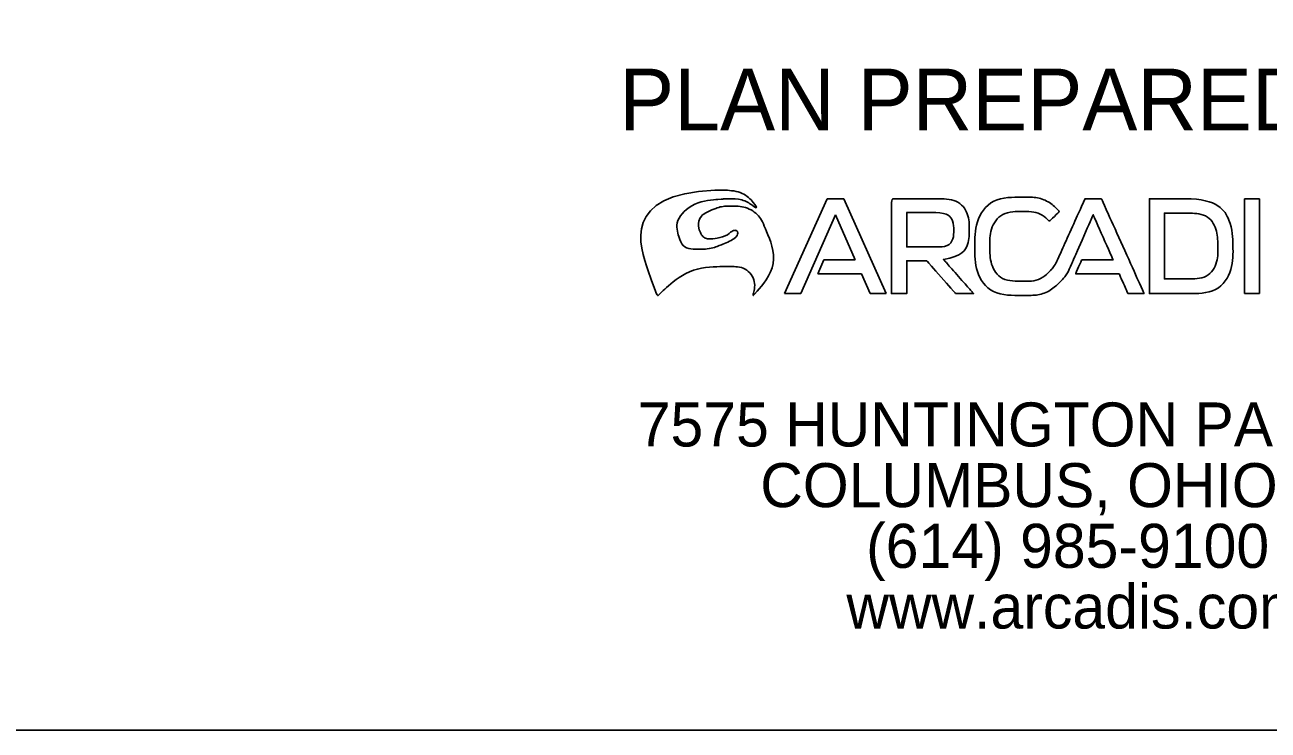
# Model space of a CAD drawing. Extents: x 0 to 45.4, y -2.2 to 22.
# Drawn here: x 2.903 to 5.724, y 0.5 to 2.102 of the extents above; entities that cross this region are included whole.
import ezdxf

# ---------------------------------------------------------------- set-up
doc = ezdxf.new("R2010")
doc.units = 0
for name, color, linetype in [('SH_Border', 7, 'Continuous'), ('SH_Data', 7, 'Continuous'), ('SH_Text', 7, 'Continuous')]:
    doc.layers.add(name, color=color, linetype=linetype)

msp = doc.modelspace()

# ---------------------------------------------------------------- linework, layer by layer
at = {"layer": 'SH_Border'}
msp.add_lwpolyline([(1.5, 21.5), (33.5, 21.5), (33.5, 0.5), (1.5, 0.5)], close=True, dxfattribs=at)
at = {"layer": 'SH_Data'}
for p, q in [((4.7232, 1.7068), (4.6265, 1.4914)), ((4.7607, 1.7068), (4.7232, 1.7068)), ((4.8574, 1.4914), (4.7607, 1.7068)), ((5.7044, 1.7068), (5.6702, 1.7068)), ((5.6702, 1.7068), (5.6702, 1.4914)), ((5.7044, 1.4914), (5.7044, 1.7068)), ((4.6632, 1.4914), (4.7419, 1.6705)), ((4.7419, 1.6705), (4.787, 1.568)), ((4.7158, 1.568), (4.7019, 1.5366)), ((4.787, 1.568), (4.7158, 1.568)), ((4.7019, 1.5366), (4.8008, 1.5366)), ((4.8008, 1.5366), (4.8207, 1.4914)), ((4.6265, 1.4914), (4.6632, 1.4914)), ((4.8207, 1.4914), (4.8574, 1.4914)), ((5.6702, 1.4914), (5.7044, 1.4914)), ((5.1819, 1.2488), (5.1819, 1.2488)), ((5.1819, 1.2488), (5.1819, 1.2488)), ((5.1819, 1.2488), (5.1819, 1.2488)), ((5.1819, 1.2488), (5.1819, 1.2488)), ((5.1819, 1.2488), (5.1819, 1.2488))]:
    msp.add_line(p, q, dxfattribs=at)
for points, degree in [([(4.4684, 1.7265), (4.2565, 1.7172), (4.3378, 1.4846), (4.3378, 1.4846), (4.3563, 1.5046), (4.4158, 1.5524), (4.4992, 1.5528), (4.4993, 1.5528), (4.4994, 1.5528), (4.4995, 1.5528), (4.5397, 1.5528), (4.5634, 1.5186), (4.5542, 1.4846), (4.5542, 1.4846), (4.6169, 1.558), (4.582, 1.6416), (4.5704, 1.6694), (4.5392, 1.6901), (4.5027, 1.6901), (4.4903, 1.6901), (4.4773, 1.6878), (4.4643, 1.6825), (4.4337, 1.6701), (4.4296, 1.6425), (4.4359, 1.6297), (4.4405, 1.6203), (4.4495, 1.6157), (4.4593, 1.6157), (4.461, 1.6157), (4.4626, 1.6158), (4.4643, 1.6161), (4.495, 1.6209), (4.5075, 1.6351), (4.5146, 1.6351), (4.5156, 1.6351), (4.5165, 1.6348), (4.5174, 1.6342), (4.5219, 1.6307), (4.5175, 1.6162), (4.4782, 1.6004), (4.4687, 1.5966), (4.4513, 1.5921), (4.4341, 1.5921), (4.414, 1.5921), (4.3943, 1.5982), (4.3877, 1.6184), (4.3753, 1.656), (4.4196, 1.701), (4.486, 1.7062), (4.4893, 1.7065), (4.4939, 1.7066), (4.4971, 1.7066), (4.5309, 1.7066), (4.5551, 1.6914), (4.5671, 1.6814), (4.5533, 1.7044), (4.5244, 1.7257), (4.4776, 1.7265), (4.4776, 1.7265), (4.4738, 1.7266), (4.4684, 1.7265), (4.4684, 1.7265), (4.4684, 1.7265), (4.4684, 1.7265)], 3), ([(4.9871, 1.5692), (5.0296, 1.5754), (5.0456, 1.6056), (5.0456, 1.6363), (5.0456, 1.6727), (5.0194, 1.7068), (4.9695, 1.7068), (4.936, 1.7068), (4.9028, 1.7068), (4.8692, 1.7068), (4.8692, 1.7068), (4.8692, 1.4914), (4.8692, 1.4914), (4.8692, 1.4914), (4.9037, 1.4914), (4.9037, 1.4914), (4.9037, 1.4914), (4.9037, 1.5659), (4.9037, 1.5659), (4.9037, 1.5659), (4.9492, 1.5659), (4.9492, 1.5659), (4.9492, 1.5659), (5.0148, 1.4914), (5.0148, 1.4914), (5.0148, 1.4914), (5.0552, 1.4914), (5.0552, 1.4914)], 3), ([(5.3456, 1.7068), (5.3456, 1.7068), (5.3081, 1.7068), (5.3081, 1.7068), (5.3081, 1.7068), (5.2454, 1.5671), (5.2454, 1.5671), (5.2454, 1.5671), (5.2454, 1.5671), (5.2454, 1.5671), (5.2387, 1.5538), (5.2313, 1.5454), (5.2287, 1.5426), (5.2136, 1.5276), (5.1916, 1.5194), (5.1717, 1.5194), (5.1159, 1.5194), (5.0926, 1.5585), (5.0922, 1.5979), (5.0919, 1.6376), (5.1169, 1.6779), (5.1717, 1.6779), (5.1917, 1.6779), (5.212, 1.6708), (5.2274, 1.6557), (5.2274, 1.6557), (5.2504, 1.6779), (5.2504, 1.6779), (5.2286, 1.6998), (5.2006, 1.7105), (5.1717, 1.7105), (5.0947, 1.7105), (5.0578, 1.6542), (5.0581, 1.5976), (5.0584, 1.5409), (5.0935, 1.4871), (5.1717, 1.4871), (5.2018, 1.4871), (5.2304, 1.4972), (5.2526, 1.5191), (5.2526, 1.5191), (5.2663, 1.5328), (5.2752, 1.553), (5.2752, 1.553), (5.2779, 1.5592), (5.2779, 1.5592), (5.2779, 1.5592), (5.2842, 1.5735), (5.2842, 1.5735), (5.2842, 1.5735), (5.2842, 1.5735), (5.2842, 1.5735), (5.2842, 1.5735), (5.3268, 1.6705), (5.3268, 1.6705), (5.3268, 1.6705), (5.3719, 1.568), (5.3719, 1.568), (5.3719, 1.568), (5.3007, 1.568), (5.3007, 1.568), (5.3007, 1.568), (5.2868, 1.5366), (5.2868, 1.5366), (5.2868, 1.5366), (5.3857, 1.5366), (5.3857, 1.5366), (5.3857, 1.5366), (5.4056, 1.4914), (5.4056, 1.4914), (5.4056, 1.4914), (5.4423, 1.4914), (5.4423, 1.4914), (5.4423, 1.4914), (5.3456, 1.7068), (5.3456, 1.7068), (5.3456, 1.7068), (5.3456, 1.7068), (5.3456, 1.7068)], 3), ([(5.5358, 1.7068), (5.5358, 1.7068), (5.4542, 1.7068), (5.4542, 1.7068)], 2), ([(5.4542, 1.7068), (5.4542, 1.7068), (5.4542, 1.4914), (5.4542, 1.4914), (5.4542, 1.4914), (5.5358, 1.4914), (5.5358, 1.4914), (5.6112, 1.4914), (5.645, 1.5465), (5.6438, 1.601), (5.6429, 1.6542), (5.6093, 1.7068), (5.5358, 1.7068)], 3), ([(4.9037, 1.6754), (4.9037, 1.6754), (4.9695, 1.6754), (4.9695, 1.6754)], 2), ([(4.9695, 1.6754), (4.9979, 1.6754), (5.0105, 1.6551), (5.0105, 1.6357), (5.0105, 1.6154), (4.9979, 1.5973), (4.9692, 1.5973), (4.9692, 1.5973), (4.9037, 1.5973), (4.9037, 1.5973), (4.9037, 1.5973), (4.9037, 1.6754), (4.9037, 1.6754)], 3), ([(5.4884, 1.5246), (5.4884, 1.5246), (5.4884, 1.6739), (5.4884, 1.6739)], 2), ([(5.4884, 1.6739), (5.4884, 1.6739), (5.5358, 1.6739), (5.5358, 1.6739), (5.5865, 1.6739), (5.6087, 1.6376), (5.6096, 1.6013), (5.6105, 1.5634), (5.5884, 1.5246), (5.5358, 1.5246), (5.5358, 1.5246), (5.4884, 1.5246), (5.4884, 1.5246)], 3), ([(5.0552, 1.4914), (5.0552, 1.4914), (4.9871, 1.5692), (4.9871, 1.5692)], 2)]:
    msp.add_open_spline(points, degree=degree, dxfattribs=at)

# ---------------------------------------------------------------- texts
for s, p in [('7575 HUNTINGTON PARK DR, STE 130', (4.2934, 1.1442)), ('COLUMBUS, OHIO  43235', (4.5715, 1.0064)), ('(614) 985-9100', (4.8116, 0.8686)), ('www.arcadis.com', (4.7669, 0.7308))]:
    msp.add_text(s, height=0.1, dxfattribs=at).set_placement(p)
at = {"layer": 'SH_Text'}
msp.add_text('PLAN PREPARED BY:', height=0.14, dxfattribs=at).set_placement((4.2513, 1.8622))

doc.saveas('drawing.dxf')
